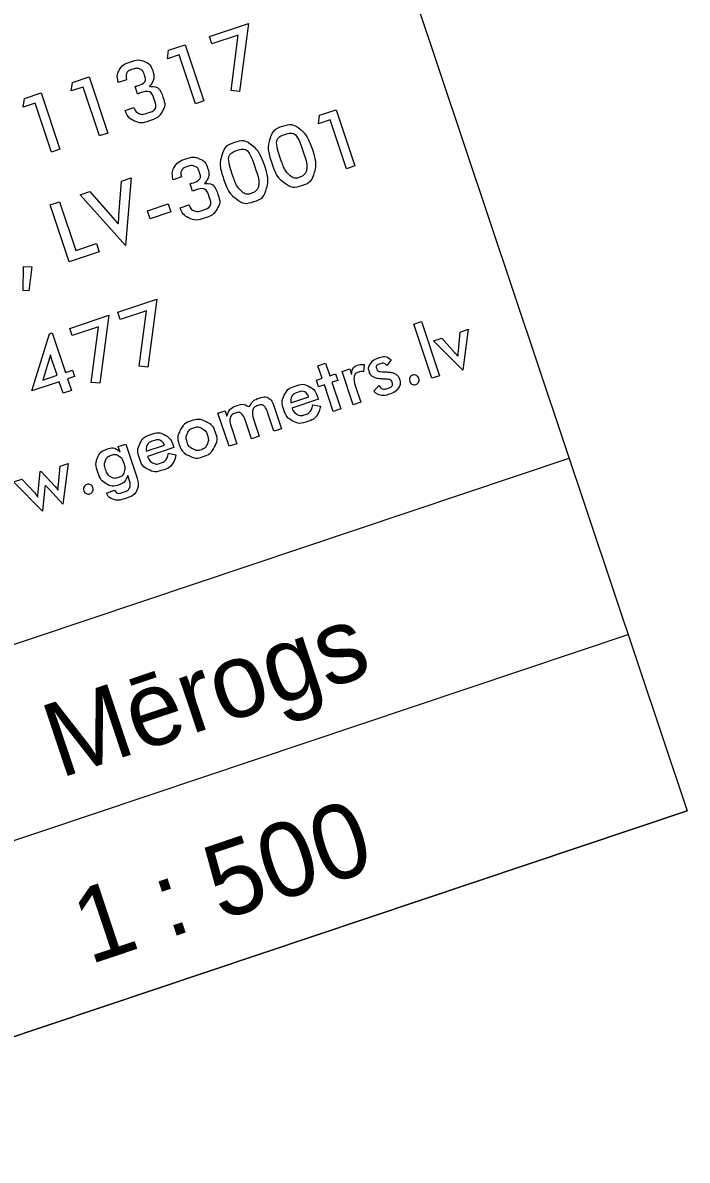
# Model space of a CAD drawing. Extents: x 469981 to 472086, y 246785 to 247785.
# Drawn here: x 471594.03 to 471602.97, y 247276.09 to 247291.38 of the extents above; entities that cross this region are included whole.
import ezdxf

# ---------------------------------------------------------------- set-up
doc = ezdxf.new("R2010")
doc.units = 0
doc.layers.add('RAMI_PLAN_####_TKST_#', color=7, linetype='Continuous')

msp = doc.modelspace()

# ---------------------------------------------------------------- linework, layer by layer
at = {"layer": 'RAMI_PLAN_####_TKST_#'}
msp.add_line((471602.966, 247280.789), (471515.262, 247251.39), dxfattribs=at)
msp.add_lwpolyline([(471602.966, 247280.789), (471091.912, 247109.483), (470998.155, 247389.187), (471509.208, 247560.493)], close=True, dxfattribs=at)
for points in [[(471596.829, 247290.469), (471596.925, 247291.216), (471596.572, 247291.098), (471596.539, 247291.196), (471597.066, 247291.373), (471596.944, 247290.458), (471596.829, 247290.469)], [(471596.352, 247290.292), (471596.131, 247290.95), (471595.973, 247290.897), (471595.988, 247291.011), (471596.211, 247291.086), (471596.465, 247290.33), (471596.352, 247290.292)], [(471595.06, 247289.859), (471594.839, 247290.517), (471594.681, 247290.464), (471594.696, 247290.578), (471594.92, 247290.653), (471595.173, 247289.897), (471595.06, 247289.859)], [(471595.425, 247290.615), (471595.313, 247290.577)], [(471595.573, 247290.425), (471595.54, 247290.524)], [(471594.414, 247289.642), (471594.194, 247290.301), (471594.035, 247290.248), (471594.05, 247290.362), (471594.274, 247290.437), (471594.527, 247289.68), (471594.414, 247289.642)], [(471595.404, 247290.201), (471595.523, 247290.241), (471595.525, 247290.235)], [(471598.383, 247289.418), (471598.162, 247290.076), (471598.004, 247290.023), (471598.019, 247290.137), (471598.242, 247290.212), (471598.496, 247289.456), (471598.383, 247289.418)], [(471595.321, 247288.789), (471595.356, 247289.253), (471595.484, 247289.296), (471595.409, 247288.388)], [(471596.164, 247289.308), (471596.052, 247289.271)], [(471596.312, 247289.118), (471596.279, 247289.217)], [(471595.409, 247288.388), (471594.802, 247289.068), (471594.931, 247289.111), (471595.239, 247288.761)], [(471594.654, 247288.168), (471594.398, 247288.932), (471594.521, 247288.973), (471594.74, 247288.321), (471595.018, 247288.414), (471595.055, 247288.302), (471594.654, 247288.168)], [(471595.706, 247288.852), (471595.985, 247288.945), (471596.02, 247288.841), (471595.741, 247288.747), (471595.706, 247288.852)], [(471596.143, 247288.894), (471596.262, 247288.934), (471596.265, 247288.928)], [(471594.038, 247288.106), (471594.152, 247288.102), (471594.11, 247287.777), (471594.034, 247287.781), (471594.038, 247288.106)], [(471595.595, 247286.763), (471595.692, 247287.509), (471595.339, 247287.391), (471595.306, 247287.489), (471595.833, 247287.666), (471595.711, 247286.752), (471595.595, 247286.763)], [(471594.95, 247286.546), (471595.047, 247287.293), (471594.693, 247287.175), (471594.66, 247287.273), (471595.187, 247287.449), (471595.066, 247286.535), (471594.95, 247286.546)], [(471599.531, 247286.602), (471599.287, 247287.33), (471599.389, 247287.364), (471599.633, 247286.636), (471599.531, 247286.602)], [(471594.57, 247286.401), (471594.518, 247286.556), (471594.152, 247286.434), (471594.39, 247287.199), (471594.425, 247287.211), (471594.603, 247286.681), (471594.696, 247286.712), (471594.725, 247286.625), (471594.632, 247286.594), (471594.684, 247286.439), (471594.57, 247286.401)], [(471599.888, 247286.968), (471599.91, 247287.224), (471600.021, 247287.261), (471599.945, 247286.71)], [(471599.945, 247286.71), (471599.553, 247287.105), (471599.665, 247287.142), (471599.837, 247286.95)], [(471594.401, 247286.918), (471594.298, 247286.579), (471594.489, 247286.643), (471594.423, 247286.842)], [(471598.983, 247286.85), (471598.927, 247286.776)], [(471598.205, 247286.157), (471598.086, 247286.514), (471598.008, 247286.488), (471597.978, 247286.577), (471598.056, 247286.603), (471597.999, 247286.771), (471598.101, 247286.805), (471598.158, 247286.637), (471598.236, 247286.663), (471598.266, 247286.574), (471598.187, 247286.548), (471598.307, 247286.191), (471598.205, 247286.157)], [(471598.509, 247286.476), (471598.575, 247286.281), (471598.473, 247286.247), (471598.323, 247286.693), (471598.425, 247286.727), (471598.449, 247286.655)], [(471598.621, 247286.787), (471598.613, 247286.688)], [(471598.749, 247286.429), (471598.818, 247286.504)], [(471597.632, 247286.273), (471597.876, 247286.355)], [(471598.005, 247286.321), (471597.649, 247286.202)], [(471597.929, 247286.246), (471598.031, 247286.226)], [(471597.998, 247286.341), (471598.005, 247286.321)], [(471596.906, 247285.722), (471596.804, 247285.688), (471596.654, 247286.133), (471596.75, 247286.165), (471596.775, 247286.092)], [(471597.406, 247286.23), (471597.509, 247285.924), (471597.407, 247285.89), (471597.33, 247286.119)], [(471596.838, 247285.925), (471596.906, 247285.722)], [(471597.141, 247286.026), (471597.209, 247285.823), (471597.106, 247285.789), (471597.029, 247286.018)], [(471595.336, 247285.61), (471595.311, 247285.683), (471595.413, 247285.717), (471595.553, 247285.299)], [(471595.69, 247285.622), (471595.933, 247285.703)], [(471596.062, 247285.67), (471595.706, 247285.551)], [(471596.056, 247285.689), (471596.062, 247285.67)], [(471577.673, 247277.584), (471601.376, 247285.529)], [(471595.987, 247285.594), (471596.089, 247285.575)], [(471594.234, 247285.072), (471594.263, 247285.349), (471594.271, 247285.352), (471594.462, 247285.149)], [(471594.507, 247285.173), (471594.532, 247285.422), (471594.64, 247285.458), (471594.567, 247284.908)], [(471594.321, 247285.087), (471594.294, 247284.816), (471593.905, 247285.212), (471594.014, 247285.248), (471594.186, 247285.067)], [(471595.461, 247285.236), (471595.441, 247285.295)], [(471594.567, 247284.908), (471594.386, 247285.105)], [(471595.154, 247285.06), (471595.264, 247285.097)], [(471578.467, 247275.213), (471602.171, 247283.159)], [(471579.262, 247272.843), (471602.966, 247280.789)]]:
    msp.add_lwpolyline(points, dxfattribs=at)
for points, degree in [([(471595.313, 247290.577), (471595.285, 247290.676), (471595.329, 247290.749), (471595.372, 247290.822), (471595.481, 247290.858), (471595.587, 247290.894), (471595.666, 247290.859), (471595.746, 247290.824), (471595.777, 247290.731), (471595.8, 247290.661), (471595.781, 247290.604), (471595.762, 247290.548), (471595.703, 247290.517), (471595.86, 247290.541), (471595.918, 247290.369), (471595.951, 247290.269), (471595.901, 247290.186), (471595.851, 247290.101), (471595.727, 247290.06), (471595.617, 247290.023), (471595.529, 247290.061), (471595.442, 247290.099), (471595.404, 247290.201)], 3), ([(471595.54, 247290.524), (471595.543, 247290.525), (471595.551, 247290.527), (471595.559, 247290.53), (471595.562, 247290.531), (471595.699, 247290.577), (471595.662, 247290.689), (471595.645, 247290.738), (471595.604, 247290.757), (471595.564, 247290.775), (471595.511, 247290.758), (471595.394, 247290.718), (471595.425, 247290.615)], 3), ([(471595.525, 247290.235), (471595.543, 247290.182), (471595.589, 247290.162), (471595.636, 247290.143), (471595.698, 247290.164), (471595.843, 247290.212), (471595.798, 247290.347), (471595.751, 247290.485), (471595.596, 247290.433), (471595.593, 247290.432), (471595.585, 247290.429), (471595.577, 247290.427), (471595.573, 247290.425)], 3), ([(471597.928, 247289.674), (471597.99, 247289.491), (471597.951, 247289.364), (471597.911, 247289.237), (471597.784, 247289.194), (471597.655, 247289.151), (471597.547, 247289.23), (471597.44, 247289.309), (471597.376, 247289.499), (471597.313, 247289.687), (471597.352, 247289.815), (471597.39, 247289.943), (471597.52, 247289.987), (471597.65, 247290.03), (471597.756, 247289.951), (471597.863, 247289.87), (471597.928, 247289.674)], 3), ([(471597.746, 247289.3), (471597.899, 247289.352), (471597.801, 247289.642), (471597.705, 247289.931), (471597.556, 247289.881), (471597.403, 247289.83), (471597.5, 247289.539), (471597.547, 247289.399), (471597.611, 247289.338), (471597.675, 247289.276), (471597.746, 247289.3)], 3), ([(471597.283, 247289.458), (471597.344, 247289.275), (471597.305, 247289.148), (471597.266, 247289.02), (471597.138, 247288.978), (471597.009, 247288.934), (471596.901, 247289.013), (471596.794, 247289.093), (471596.73, 247289.282), (471596.667, 247289.47), (471596.706, 247289.598), (471596.744, 247289.727), (471596.874, 247289.77), (471597.004, 247289.814), (471597.11, 247289.734), (471597.217, 247289.654), (471597.283, 247289.458)], 3), ([(471597.1, 247289.084), (471597.253, 247289.135), (471597.155, 247289.426), (471597.059, 247289.715), (471596.91, 247289.665), (471596.757, 247289.614), (471596.855, 247289.323), (471596.902, 247289.182), (471596.965, 247289.121), (471597.029, 247289.06), (471597.1, 247289.084)], 3), ([(471596.052, 247289.271), (471596.025, 247289.369), (471596.068, 247289.442), (471596.111, 247289.515), (471596.221, 247289.551), (471596.326, 247289.587), (471596.406, 247289.552), (471596.485, 247289.517), (471596.516, 247289.425), (471596.54, 247289.354), (471596.52, 247289.297), (471596.501, 247289.241), (471596.442, 247289.21), (471596.6, 247289.234), (471596.657, 247289.063), (471596.691, 247288.962), (471596.641, 247288.879), (471596.59, 247288.794), (471596.467, 247288.753), (471596.357, 247288.716), (471596.269, 247288.754), (471596.181, 247288.792), (471596.143, 247288.894)], 3), ([(471596.279, 247289.217), (471596.283, 247289.218), (471596.29, 247289.22), (471596.298, 247289.223), (471596.302, 247289.224), (471596.439, 247289.27), (471596.401, 247289.382), (471596.385, 247289.431), (471596.344, 247289.45), (471596.303, 247289.468), (471596.251, 247289.451), (471596.133, 247289.411), (471596.164, 247289.308)], 3), ([(471596.265, 247288.928), (471596.282, 247288.875), (471596.329, 247288.855), (471596.375, 247288.836), (471596.437, 247288.857), (471596.582, 247288.905), (471596.537, 247289.04), (471596.491, 247289.178), (471596.336, 247289.126), (471596.332, 247289.125), (471596.324, 247289.122), (471596.316, 247289.12), (471596.312, 247289.118)], 3), ([(471595.239, 247288.761), (471595.292, 247288.701), (471595.321, 247288.652), (471595.316, 247288.712), (471595.321, 247288.789)], 3), ([(471594.423, 247286.842), (471594.412, 247286.873), (471594.401, 247286.918)], 2), ([(471598.818, 247286.504), (471598.86, 247286.442), (471598.941, 247286.469), (471599.014, 247286.494), (471598.995, 247286.552), (471598.985, 247286.582), (471598.949, 247286.588), (471598.906, 247286.59), (471598.864, 247286.593), (471598.787, 247286.599), (471598.749, 247286.618), (471598.706, 247286.639), (471598.69, 247286.685), (471598.671, 247286.744), (471598.704, 247286.797), (471598.738, 247286.85), (471598.816, 247286.876), (471598.923, 247286.912), (471598.983, 247286.85)], 3), ([(471599.837, 247286.95), (471599.856, 247286.93), (471599.889, 247286.878), (471599.884, 247286.922), (471599.888, 247286.968)], 3), ([(471598.449, 247286.655), (471598.452, 247286.753), (471598.53, 247286.779), (471598.574, 247286.793), (471598.621, 247286.787)], 3), ([(471598.613, 247286.688), (471598.581, 247286.697), (471598.545, 247286.685), (471598.492, 247286.668), (471598.485, 247286.616), (471598.478, 247286.569), (471598.509, 247286.476)], 3), ([(471598.927, 247286.776), (471598.894, 247286.816), (471598.838, 247286.797), (471598.773, 247286.776), (471598.79, 247286.725), (471598.8, 247286.697), (471598.838, 247286.691), (471598.886, 247286.689), (471598.934, 247286.686), (471599.002, 247286.682), (471599.038, 247286.662), (471599.077, 247286.64), (471599.093, 247286.593), (471599.115, 247286.527), (471599.08, 247286.473), (471599.045, 247286.418), (471598.959, 247286.389), (471598.83, 247286.346), (471598.749, 247286.429)], 3), ([(471599.232, 247286.559), (471599.223, 247286.585), (471599.235, 247286.61), (471599.246, 247286.634), (471599.272, 247286.643), (471599.298, 247286.652), (471599.322, 247286.639), (471599.346, 247286.627), (471599.355, 247286.601), (471599.364, 247286.575), (471599.352, 247286.551), (471599.34, 247286.528), (471599.314, 247286.519), (471599.288, 247286.51), (471599.264, 247286.522), (471599.24, 247286.534), (471599.232, 247286.559)], 3), ([(471598.031, 247286.226), (471598.002, 247286.068), (471597.853, 247286.018), (471597.746, 247285.983), (471597.66, 247286.027), (471597.575, 247286.071), (471597.538, 247286.18), (471597.503, 247286.284), (471597.546, 247286.374), (471597.589, 247286.463), (471597.692, 247286.498), (471597.8, 247286.534), (471597.88, 247286.493), (471597.961, 247286.451), (471597.998, 247286.341)], 3), ([(471597.876, 247286.355), (471597.831, 247286.449), (471597.723, 247286.412), (471597.624, 247286.379), (471597.632, 247286.273)], 3), ([(471596.775, 247286.092), (471596.804, 247286.201), (471596.905, 247286.235), (471597.008, 247286.27), (471597.074, 247286.193), (471597.112, 247286.304), (471597.209, 247286.337), (471597.3, 247286.367), (471597.359, 247286.317), (471597.385, 247286.295), (471597.406, 247286.23)], 3), ([(471597.33, 247286.119), (471597.306, 247286.192), (471597.288, 247286.214), (471597.254, 247286.256), (471597.194, 247286.236), (471597.131, 247286.215), (471597.12, 247286.163), (471597.11, 247286.117), (471597.141, 247286.026)], 3), ([(471597.649, 247286.202), (471597.674, 247286.141), (471597.719, 247286.117), (471597.764, 247286.093), (471597.819, 247286.111), (471597.912, 247286.142), (471597.929, 247286.246)], 3), ([(471597.029, 247286.018), (471597.002, 247286.097), (471596.973, 247286.123), (471596.942, 247286.152), (471596.891, 247286.135), (471596.828, 247286.113), (471596.814, 247286.052), (471596.807, 247286.017), (471596.838, 247285.925)], 3), ([(471596.131, 247285.709), (471596.097, 247285.808), (471596.146, 247285.902), (471596.194, 247285.996), (471596.295, 247286.029), (471596.397, 247286.064), (471596.493, 247286.017), (471596.588, 247285.971), (471596.621, 247285.873), (471596.655, 247285.772), (471596.607, 247285.68), (471596.557, 247285.584), (471596.456, 247285.55), (471596.355, 247285.516), (471596.26, 247285.563), (471596.164, 247285.609), (471596.131, 247285.709)], 3), ([(471596.514, 247285.836), (471596.493, 247285.899), (471596.439, 247285.928), (471596.384, 247285.957), (471596.327, 247285.938), (471596.269, 247285.919), (471596.244, 247285.863), (471596.218, 247285.806), (471596.239, 247285.744), (471596.26, 247285.682), (471596.314, 247285.652), (471596.369, 247285.623), (471596.426, 247285.642), (471596.483, 247285.661), (471596.509, 247285.718), (471596.535, 247285.774), (471596.514, 247285.836)], 3), ([(471596.089, 247285.575), (471596.059, 247285.417), (471595.91, 247285.367), (471595.803, 247285.331), (471595.718, 247285.376), (471595.633, 247285.42), (471595.596, 247285.529), (471595.561, 247285.633), (471595.604, 247285.723), (471595.646, 247285.812), (471595.75, 247285.847), (471595.857, 247285.883), (471595.938, 247285.841), (471596.019, 247285.8), (471596.056, 247285.689)], 3), ([(471595.933, 247285.703), (471595.889, 247285.797), (471595.78, 247285.761), (471595.681, 247285.728), (471595.69, 247285.622)], 3), ([(471595.441, 247285.295), (471595.412, 247285.2), (471595.32, 247285.169), (471595.226, 247285.138), (471595.15, 247285.184), (471595.074, 247285.23), (471595.036, 247285.343), (471595, 247285.45), (471595.034, 247285.534), (471595.068, 247285.618), (471595.156, 247285.648), (471595.269, 247285.686), (471595.336, 247285.61)], 3), ([(471595.389, 247285.462), (471595.365, 247285.532), (471595.32, 247285.559), (471595.275, 247285.587), (471595.217, 247285.567), (471595.159, 247285.548), (471595.14, 247285.497), (471595.12, 247285.446), (471595.143, 247285.376), (471595.167, 247285.305), (471595.212, 247285.277), (471595.257, 247285.249), (471595.315, 247285.269), (471595.369, 247285.287), (471595.39, 247285.339), (471595.412, 247285.393), (471595.389, 247285.462)], 3), ([(471595.706, 247285.551), (471595.731, 247285.489), (471595.776, 247285.465), (471595.821, 247285.442), (471595.877, 247285.46), (471595.97, 247285.491), (471595.987, 247285.594)], 3), ([(471594.386, 247285.105), (471594.352, 247285.143), (471594.324, 247285.183), (471594.323, 247285.108), (471594.321, 247285.087)], 3), ([(471594.462, 247285.149), (471594.497, 247285.112), (471594.511, 247285.075), (471594.502, 247285.129), (471594.507, 247285.173)], 3), ([(471594.848, 247285.09), (471594.84, 247285.116), (471594.851, 247285.14), (471594.863, 247285.165), (471594.889, 247285.174), (471594.915, 247285.182), (471594.939, 247285.17), (471594.963, 247285.157), (471594.972, 247285.131), (471594.98, 247285.106), (471594.968, 247285.082), (471594.956, 247285.058), (471594.931, 247285.05), (471594.905, 247285.041), (471594.881, 247285.053), (471594.857, 247285.064), (471594.848, 247285.09)], 3), ([(471595.553, 247285.299), (471595.596, 247285.172), (471595.565, 247285.102), (471595.532, 247285.028), (471595.405, 247284.986), (471595.312, 247284.954), (471595.244, 247284.975), (471595.176, 247284.996), (471595.154, 247285.06)], 3), ([(471595.264, 247285.097), (471595.289, 247285.039), (471595.379, 247285.07), (471595.447, 247285.093), (471595.466, 247285.133), (471595.482, 247285.171), (471595.461, 247285.236)], 3), ([(471594.186, 247285.067), (471594.208, 247285.044), (471594.238, 247284.984), (471594.229, 247285.016), (471594.234, 247285.072)], 3)]:
    msp.add_open_spline(points, degree=degree, dxfattribs=at)

# ---------------------------------------------------------------- texts
for s, p in [('Mērogs', (471594.528, 247281.222)), ('1 : 500', (471594.925, 247278.718))]:
    msp.add_text(s, height=1, rotation=18.5312, dxfattribs=at).set_placement(p)

doc.saveas('drawing.dxf')
